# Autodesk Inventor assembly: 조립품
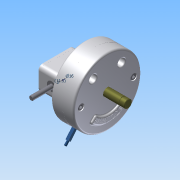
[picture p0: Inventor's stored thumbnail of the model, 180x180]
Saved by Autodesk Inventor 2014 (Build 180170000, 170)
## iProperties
Created: 2015-04
Part Number: 조립품
Document SubType Name: Assembly
Designer: Administrator
Mass: 3964.99 g
Surface Area: 3333.71 cm^2
Volume: 1140.85 cm^3
Density: 3.47547 g/cm^3
Author: Administrator
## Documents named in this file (15)
- C:\Documents and Settings\Administrator\바탕 화면\350406V1031\조립품.iam
- C:\Documents and Settings\Administrator\바탕 화면\350406V1031\본체.ipt
- C:\Documents and Settings\Administrator\바탕 화면\350406V1031\가변스프링.ipt
- C:\Documents and Settings\Administrator\바탕 화면\350406V1031\축.ipt
- C:\Documents and Settings\Administrator\바탕 화면\350406V1031\멈춤링.ipt
- C:\Documents and Settings\Administrator\바탕 화면\350406V1031\베어링62_22.ipt
- C:\Documents and Settings\Administrator\바탕 화면\350406V1031\슬라이더2.ipt
- C:\Documents and Settings\Administrator\바탕 화면\350406V1031\슬라이더.ipt
- C:\Documents and Settings\Administrator\바탕 화면\350406V1031\커버.ipt
- C:\Documents and Settings\Administrator\바탕 화면\350406V1031\커버2.ipt
- C:\Documents and Settings\Administrator\바탕 화면\350406V1031\슬라이더3.ipt
- C:\Documents and Settings\Administrator\바탕 화면\350406V1031\평행핀.ipt
- C:\Documents and Settings\Administrator\바탕 화면\350406V1031\부시.ipt
- C:\Documents and Settings\Administrator\바탕 화면\350406V1031\M 5 x 12.ipt
- C:\Documents and Settings\Administrator\바탕 화면\350406V1031\M 10 x 35.ipt
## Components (6 placed, 4 different names)
1. 가변스프링:1
2. KS B 1320 B B 5 x  20:1 — 플러쉬:1
3. M 5 x 12:1
4. M 5 x 12:2
5. M 10 x 35:1
6. M 10 x 35:2
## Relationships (1: Flush 1)
- 플러쉬:1 [Flush]: KS B 1320 B B 5 x  20:1
